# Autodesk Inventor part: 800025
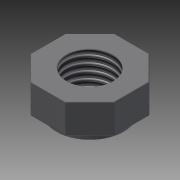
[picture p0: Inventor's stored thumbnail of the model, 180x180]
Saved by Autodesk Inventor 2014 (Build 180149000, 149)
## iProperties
Created: 2007-11
Part Number: 800025
Document SubType Name: Modeling
Designer: TH
Density: 7.85 g/cm^3
Mass: 11.5096 g
Surface Area: 11.3549 cm^2
Volume: 1.46619 cm^3
Material: Steel
Description: NUT R3423 - M12
Appearance: Light Gray
Component Category: Fasteners
Author: TH
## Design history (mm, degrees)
sketch "Sketch1"
  geometry: L1 (-12.805, 0)-(12.805, 0) reference; L2 (9.147, -3.789)-(3.789, -9.147); L3 (3.789, -9.147)-(-3.789, -9.147); L4 (-3.789, -9.147)-(-9.146, -3.789); L5 (-9.146, -3.789)-(-9.146, 3.789); L6 (-9.146, 3.789)-(-3.789, 9.146); L7 (-3.789, 9.146)-(3.789, 9.146); L8 (3.789, 9.146)-(9.146, 3.789); L9 (9.146, 3.789)-(9.147, -3.789); C1 r 5 at (0, 0); 3 further points
  constraints: 16 end point, 2 coincident, 1 centre point, 1 midpoint, 1 point on line, 17 other
  dimensions: "d0" = 18.293 distance between parallel lines of L9 L5; "d1" = 10 diameter of C1
extrude "Extrusion1" new body sketch "Sketch1" distance "d2" = 6.48; taper "d3" = 0 deg
sketch "Sketch2"
  geometry: C1 r 5 at (0, 0) reference; C2 r 7.325 at (0, 0)
  constraints: 1 centre point, 1 coincident
  dimensions: "d4" = 14.65 diameter of C2
extrude "Extrusion2" join sketch "Sketch2" distance "d5" = 2; taper "d6" = 0 deg
fillet "Fillet1" dims "d7" = 0.2
thread "Thread1" dims "d8" = 10, "d9" = 0
body "Solid1"
